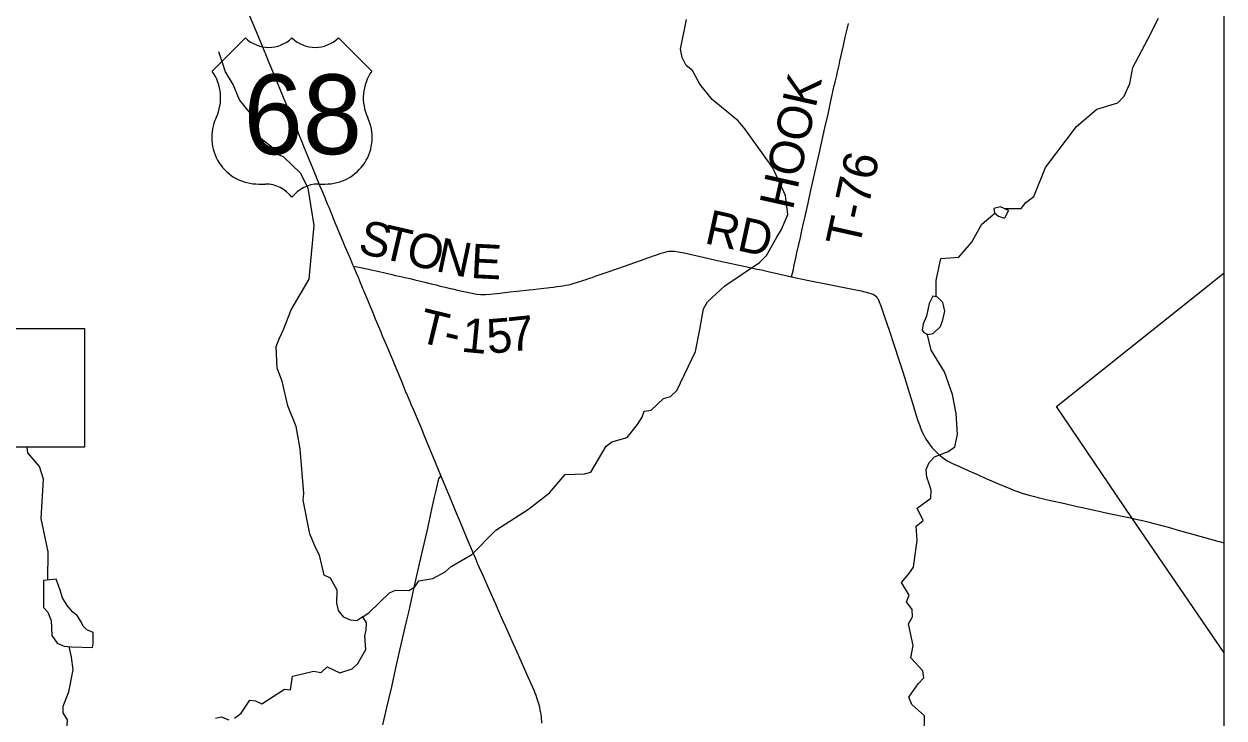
# Model space of a CAD drawing. Extents: x 0 to 34, y 0 to 22.
# Drawn here: x 14.353 to 16.337, y 19.117 to 20.264 of the extents above; entities that cross this region are included whole.
import ezdxf

# ---------------------------------------------------------------- set-up
doc = ezdxf.new("R2010")
doc.units = 0
for name, color, linetype in [('GM_X_Corporation', 7, 'Continuous'), ('GM_X_County_Road', 7, 'Continuous'), ('GM_X_Minor_Lake', 7, 'Continuous'), ('GM_X_Minor_River', 7, 'Continuous'), ('GM_X_Township_Road', 7, 'Continuous'), ('GM_X_Township_Road_Text', 7, 'Continuous'), ('GM_X_US_Location', 7, 'Continuous'), ('GM_X_US_Route', 7, 'Continuous'), ('GM_X_US_Shield', 7, 'Continuous'), ('SH_Text', 7, 'Continuous')]:
    doc.layers.add(name, color=color, linetype=linetype)

msp = doc.modelspace()

# ---------------------------------------------------------------- linework, layer by layer
at = {"layer": 'GM_X_Corporation'}
msp.add_lwpolyline([(16.3375, 14.3932), (16.3375, 21.1059), (9.5375, 21.1059), (9.5375, 15.0426), (9.5452, 15.0418), (9.7185, 15.0258), (10.2502, 14.9799), (10.3112, 14.9746), (10.787, 14.9212), (11.3129, 14.8754), (11.3292, 14.8742), (12.1361, 14.7923), (13.6754, 14.6095), (14.714, 14.5341), (15.778, 14.4476), (16.0263, 14.4243)], close=True, dxfattribs=at)
msp.add_lwpolyline([(16.3375, 19.0766), (16.3375, 19.2248), (16.1853, 19.4477), (16.0606, 19.6317), (16.3375, 19.8528), (16.3375, 21.1059)], dxfattribs=at)
at = {"layer": 'GM_X_County_Road'}
msp.add_lwpolyline([(14.9461, 19.1058), (14.9528, 19.1341), (14.9567, 19.1503), (14.9609, 19.1685), (14.9671, 19.197), (14.9734, 19.2242), (14.9832, 19.2672), (14.9859, 19.2787), (14.9891, 19.2918), (14.995, 19.3172), (14.9983, 19.3324), (15.0016, 19.3475), (15.007, 19.3718), (15.0151, 19.4069), (15.0193, 19.4257), (15.0221, 19.4384), (15.025, 19.4517), (15.028, 19.465), (15.0285, 19.4674), (15.0318, 19.482), (15.0338, 19.491), (15.0366, 19.5031), (15.0384, 19.5102), (15.0391, 19.5122), (15.0398, 19.5138), (15.0421, 19.5179)], dxfattribs=at)
at = {"layer": 'GM_X_Minor_Lake'}
for points in [[(15.9809, 19.9558), (15.9681, 19.9621), (15.957, 19.9593), (15.958, 19.952), (15.9644, 19.9466), (15.9742, 19.9434)], [(15.9809, 19.9558), (15.9742, 19.9434)], [(15.8567, 19.7525), (15.8686, 19.7641), (15.8726, 19.7754), (15.8759, 19.7894), (15.8727, 19.8039), (15.8638, 19.8128), (15.8558, 19.8144), (15.8499, 19.802), (15.8454, 19.7812), (15.8399, 19.7687)], [(15.8399, 19.7687), (15.8381, 19.7579), (15.8408, 19.7543), (15.8473, 19.7508), (15.8567, 19.7525)], [(14.4674, 19.2401), (14.4669, 19.2584), (14.4564, 19.2627), (14.4508, 19.2689), (14.4471, 19.2758), (14.4408, 19.2862), (14.4337, 19.292), (14.4244, 19.3031), (14.4163, 19.3158), (14.4127, 19.3284), (14.4058, 19.3464), (14.3848, 19.3441), (14.3848, 19.2993), (14.3923, 19.2919), (14.3978, 19.2782), (14.3989, 19.2531), (14.4078, 19.2404), (14.4191, 19.2356), (14.4312, 19.2347)], [(14.4312, 19.2347), (14.4663, 19.2332), (14.4674, 19.2401)]]:
    msp.add_lwpolyline(points, dxfattribs=at)
at = {"layer": 'GM_X_Minor_River'}
for points in [[(14.9131, 19.2841), (14.9239, 19.2912), (14.9571, 19.3236), (14.967, 19.328), (14.9894, 19.3276), (14.999, 19.3339), (15.006, 19.3437), (15.0292, 19.3478), (15.0495, 19.3585), (15.0592, 19.3674), (15.0933, 19.387), (15.1331, 19.4277), (15.1869, 19.4621), (15.2219, 19.4892), (15.2478, 19.5195), (15.2797, 19.5205), (15.29, 19.5234), (15.3155, 19.5666), (15.3251, 19.5733), (15.3503, 19.5808), (15.3677, 19.6022), (15.3751, 19.6142), (15.3783, 19.6244), (15.3901, 19.6257), (15.4106, 19.6451), (15.422, 19.6487), (15.4325, 19.6584), (15.4632, 19.7228), (15.4706, 19.7591), (15.4765, 19.7932), (15.4832, 19.8052), (15.5121, 19.8317), (15.5694, 19.8702), (15.5806, 19.8818), (15.5978, 19.9122), (15.6056, 19.9246), (15.6159, 19.9492), (15.6123, 19.9811), (15.5914, 20.0267), (15.545, 20.0912), (15.5342, 20.1043), (15.4908, 20.1396), (15.4704, 20.1647), (15.4586, 20.1873), (15.4481, 20.1958), (15.4411, 20.2092), (15.4387, 20.2229), (15.4486, 20.2718)], [(15.9738, 19.9593), (16.0018, 19.9592), (16.0096, 19.9694), (16.0227, 19.979), (16.0421, 20.0269), (16.0934, 20.0951), (16.1269, 20.1238), (16.162, 20.1338), (16.1724, 20.145), (16.1815, 20.1658), (16.1865, 20.1923), (16.2113, 20.2393), (16.2289, 20.2743)], [(14.701, 19.1165), (14.7118, 19.1251), (14.7262, 19.1461), (14.7357, 19.1455), (14.7459, 19.1404), (14.7835, 19.1645), (14.7937, 19.1635), (14.7971, 19.1863), (14.8109, 19.1894), (14.8318, 19.1944), (14.8443, 19.1923), (14.8544, 19.2016), (14.8751, 19.1914), (14.8953, 19.1979), (14.9049, 19.2068), (14.9179, 19.2301), (14.9164, 19.2522), (14.9184, 19.262), (14.919, 19.2742), (14.9131, 19.2841), (14.9035, 19.2778), (14.8925, 19.2784), (14.8816, 19.2835), (14.873, 19.2947), (14.8702, 19.3069), (14.8706, 19.3282), (14.8595, 19.3481), (14.849, 19.3528), (14.8416, 19.386), (14.8346, 19.3986), (14.8255, 19.4216), (14.8143, 19.4772), (14.8156, 19.4882), (14.8093, 19.562), (14.8027, 19.5989), (14.7892, 19.633), (14.78, 19.6741), (14.7717, 19.6955), (14.77, 19.7309), (14.7756, 19.7452), (14.7819, 19.7592), (14.7946, 19.7916), (14.8243, 19.8424), (14.8327, 19.9311), (14.8227, 19.9928), (14.8102, 20.018), (14.7822, 20.0447), (14.772, 20.0487), (14.7627, 20.061), (14.7399, 20.0785), (14.7346, 20.1052), (14.728, 20.1159), (14.7094, 20.139), (14.6988, 20.1646), (14.6859, 20.1854), (14.6751, 20.2186)], [(15.8612, 19.8133), (15.8612, 19.8405), (15.869, 19.8765), (15.8987, 19.879), (15.92, 19.9029), (15.9368, 19.9334), (15.9587, 19.9514)], [(15.8416, 19.0905), (15.8424, 19.1205), (15.8211, 19.1391), (15.816, 19.1513), (15.8316, 19.1734), (15.8412, 19.1835), (15.8395, 19.195), (15.8198, 19.2162), (15.8232, 19.2366), (15.8154, 19.2728), (15.8225, 19.2841), (15.8219, 19.2963), (15.8123, 19.309), (15.8166, 19.3199), (15.8041, 19.341), (15.8161, 19.3552), (15.8242, 19.3661), (15.8299, 19.4108), (15.8281, 19.434), (15.84, 19.4433), (15.8301, 19.464), (15.8528, 19.4803), (15.8534, 19.4936), (15.8501, 19.5039), (15.8458, 19.5153), (15.8448, 19.5275), (15.85, 19.5392), (15.8589, 19.5489), (15.8814, 19.5576), (15.8922, 19.5651), (15.8967, 19.5859), (15.8943, 19.6205), (15.8884, 19.6517), (15.8753, 19.6895), (15.8532, 19.7252), (15.8468, 19.7527)], [(14.3919, 19.3449), (14.3929, 19.3918), (14.3813, 19.4467), (14.3851, 19.5119), (14.3786, 19.5329), (14.3592, 19.5553), (14.3579, 19.5648)], [(14.4628, 19.0015), (14.4475, 19.0107), (14.4245, 19.0419), (14.4206, 19.0571), (14.4249, 19.1137), (14.4176, 19.1252), (14.4174, 19.1366), (14.4269, 19.1599), (14.434, 19.1963), (14.4313, 19.2176), (14.4274, 19.235)], [(14.6695, 19.1167), (14.679, 19.1188), (14.6915, 19.1136)]]:
    msp.add_lwpolyline(points, dxfattribs=at)
at = {"layer": 'GM_X_Township_Road'}
for points in [[(15.6224, 19.8463), (15.6252, 19.8586), (15.6262, 19.8635), (15.6287, 19.875), (15.6311, 19.8859), (15.6342, 19.8999), (15.6368, 19.9114), (15.6393, 19.9229), (15.642, 19.935), (15.6441, 19.9441), (15.6452, 19.949), (15.6497, 19.9682), (15.6544, 19.9895), (15.663, 20.0283), (15.6678, 20.0495), (15.6775, 20.0925), (15.6826, 20.1156), (15.6873, 20.1374), (15.6895, 20.1471), (15.6913, 20.155), (15.693, 20.1629), (15.6943, 20.1683), (15.6953, 20.1725), (15.6969, 20.1792), (15.6983, 20.1852), (15.7008, 20.1961), (15.7022, 20.2028), (15.7079, 20.2289), (15.7111, 20.2428), (15.7136, 20.2537), (15.7146, 20.258), (15.7163, 20.2652)], [(14.8976, 19.8642), (14.9072, 19.8621), (14.92, 19.8594), (14.94, 19.8549), (14.9493, 19.8527), (14.9611, 19.8502), (14.9673, 19.8488), (14.9732, 19.8475), (14.9833, 19.8451), (14.9936, 19.8428), (14.999, 19.8415), (15.0065, 19.8397), (15.0155, 19.8375), (15.0262, 19.8348), (15.0342, 19.8329), (15.0396, 19.8315), (15.0517, 19.8286), (15.0583, 19.8271), (15.0613, 19.8264), (15.0722, 19.8239), (15.0831, 19.8214), (15.0909, 19.8197), (15.0938, 19.8191), (15.0985, 19.8183), (15.1021, 19.8178), (15.1085, 19.8173), (15.1123, 19.8172), (15.1159, 19.8173), (15.1239, 19.8177), (15.1344, 19.8188), (15.1399, 19.8195), (15.1442, 19.82), (15.1565, 19.8213), (15.1677, 19.8225), (15.1883, 19.8248), (15.1949, 19.8256), (15.2034, 19.8266), (15.2127, 19.8276), (15.2182, 19.8281), (15.2225, 19.8286), (15.2287, 19.8294), (15.2339, 19.8301), (15.2403, 19.8309), (15.2441, 19.8316), (15.2488, 19.8323), (15.2534, 19.8332), (15.2576, 19.8343), (15.2643, 19.8362), (15.2667, 19.837), (15.2697, 19.8379), (15.2724, 19.8387), (15.2754, 19.8397), (15.2789, 19.8409), (15.2828, 19.8422), (15.2879, 19.8439), (15.2922, 19.8454), (15.2977, 19.8473), (15.314, 19.8529), (15.3367, 19.8608), (15.3725, 19.8733), (15.383, 19.877), (15.3986, 19.8826), (15.4067, 19.8854), (15.4133, 19.8874), (15.4167, 19.8882), (15.4193, 19.8886), (15.4247, 19.8889), (15.4286, 19.8887), (15.4345, 19.8879), (15.4381, 19.8872), (15.4444, 19.8859), (15.4709, 19.8799), (15.5019, 19.8728), (15.5202, 19.8689), (15.5512, 19.8623), (15.5627, 19.8598), (15.5724, 19.8578), (15.5858, 19.8548), (15.5936, 19.853), (15.6224, 19.8463)], [(15.6224, 19.8463), (15.6483, 19.8411), (15.6872, 19.833), (15.7201, 19.8264), (15.7372, 19.823), (15.7497, 19.82), (15.7536, 19.8188), (15.7566, 19.8178), (15.759, 19.8165), (15.761, 19.815), (15.7621, 19.8139), (15.7635, 19.8124), (15.7648, 19.8105), (15.7661, 19.8081), (15.7674, 19.8051), (15.77, 19.7986), (15.7766, 19.7785), (15.7835, 19.7579), (15.7919, 19.7326), (15.8009, 19.7056), (15.8057, 19.691), (15.8118, 19.6716), (15.8164, 19.6568), (15.8202, 19.6445), (15.8308, 19.6101), (15.8348, 19.599)], [(15.8348, 19.599), (15.8352, 19.5979), (15.839, 19.5883), (15.8409, 19.5843), (15.8439, 19.5789), (15.8485, 19.5717), (15.8545, 19.564), (15.8602, 19.558), (15.8656, 19.5526), (15.8715, 19.5479), (15.8797, 19.5423), (15.8884, 19.5376), (15.8999, 19.5325), (15.9156, 19.5256)], [(15.9156, 19.5256), (15.9258, 19.5212), (15.9405, 19.5146), (15.962, 19.5054), (15.9833, 19.4965), (15.9908, 19.4933), (15.996, 19.4913), (16.0003, 19.4897), (16.0055, 19.488), (16.0152, 19.4851), (16.0242, 19.4829), (16.032, 19.481), (16.0368, 19.4799), (16.0434, 19.4783), (16.0483, 19.4772), (16.0743, 19.4713), (16.0949, 19.4667), (16.1058, 19.4644), (16.1179, 19.4617), (16.1313, 19.4588), (16.1398, 19.4569), (16.1531, 19.454), (16.1719, 19.4499), (16.1855, 19.4471)], [(16.1855, 19.4471), (16.1889, 19.4464), (16.2028, 19.4433), (16.2094, 19.4417), (16.2473, 19.4316), (16.258, 19.4286), (16.3273, 19.4091), (16.3375, 19.4063)]]:
    msp.add_lwpolyline(points, dxfattribs=at)
at = {"layer": 'GM_X_US_Route'}
msp.add_lwpolyline([(15.209, 19.1081), (15.2084, 19.1187), (15.208, 19.1222), (15.2076, 19.1254), (15.2067, 19.1302), (15.2057, 19.1346), (15.2043, 19.1404), (15.2023, 19.147), (15.1997, 19.1542), (15.1982, 19.1581), (15.197, 19.161), (15.1943, 19.1672), (15.1915, 19.1735), (15.1846, 19.1892), (15.1749, 19.2109), (15.1683, 19.2257), (15.1625, 19.2388), (15.1542, 19.2575), (15.1519, 19.2625), (15.1496, 19.2676), (15.1453, 19.2772), (15.137, 19.2959), (15.1329, 19.305), (15.1226, 19.3283), (15.1166, 19.3419), (15.1114, 19.3538), (15.1063, 19.3652), (15.1036, 19.3714), (15.0999, 19.3799), (15.0977, 19.3851), (15.0945, 19.3925), (15.0858, 19.4131), (15.0746, 19.44), (15.0664, 19.4595), (15.0568, 19.4827), (15.0434, 19.5149), (15.0421, 19.5179), (15.0293, 19.5487), (15.017, 19.5789), (15.0094, 19.5972), (15.0034, 19.6115), (14.9967, 19.6269), (14.9932, 19.6355), (14.992, 19.6384), (14.9869, 19.6504), (14.984, 19.6573), (14.9774, 19.6733), (14.9699, 19.6917), (14.9655, 19.702), (14.9626, 19.7089), (14.9587, 19.718), (14.9548, 19.7271), (14.951, 19.7363), (14.9459, 19.7483), (14.9433, 19.7546), (14.9378, 19.7677), (14.9342, 19.7763), (14.9295, 19.7878), (14.9247, 19.7993), (14.9212, 19.8079), (14.9181, 19.8153), (14.9148, 19.8233), (14.9092, 19.8365), (14.9058, 19.8451), (14.9025, 19.8525), (14.8976, 19.8642), (14.8967, 19.8662), (14.8931, 19.8748), (14.8869, 19.8897), (14.8841, 19.8959), (14.8808, 19.904), (14.8649, 19.9424), (14.863, 19.947), (14.8573, 19.9608), (14.8549, 19.9665), (14.8502, 19.978), (14.8459, 19.9883), (14.8428, 19.9958), (14.8315, 20.0233), (14.8223, 20.0458), (14.8168, 20.0589), (14.8126, 20.0693), (14.8072, 20.0825), (14.8054, 20.0871), (14.8033, 20.0923), (14.795, 20.1124), (14.7892, 20.1258), (14.7848, 20.1364), (14.7822, 20.1427), (14.7782, 20.1525), (14.771, 20.1697), (14.7679, 20.1771), (14.7643, 20.1857), (14.7598, 20.1966), (14.7567, 20.204), (14.7525, 20.2143), (14.7512, 20.2178), (14.7401, 20.2448), (14.7225, 20.2866)], dxfattribs=at)
at = {"layer": 'GM_X_US_Shield'}
for p, q in [((14.719, 20.2415), (14.6641, 20.1866)), ((14.9278, 20.1866), (14.8728, 20.2415)), ((14.741, 19.9998), (14.752, 19.9998)), ((14.8399, 19.9998), (14.8509, 19.9998))]:
    msp.add_line(p, q, dxfattribs=at)
for centre, radius, start, end in [((14.7575, 20.2807), 0.0549, 225.573, 314.427), ((14.8344, 20.2807), 0.0549, 225.573, 314.427), ((14.6011, 20.1425), 0.0769, 334.5471, 35.0009), ((14.9908, 20.1425), 0.0769, 144.9991, 205.4529), ((14.7401, 20.0767), 0.0769, 154.8319, 270.6383), ((14.8517, 20.0767), 0.0769, 269.3617, 25.1681), ((14.752, 19.9449), 0.0549, 36.8699, 90), ((14.8399, 19.9449), 0.0549, 90, 143.1301)]:
    msp.add_arc(centre, radius, start, end, dxfattribs=at)
at = {"layer": 'SH_Text'}
msp.add_lwpolyline([(13.1377, 19.7608), (14.4527, 19.7608), (14.4527, 19.5648), (13.1377, 19.5648)], close=True, dxfattribs=at)

# ---------------------------------------------------------------- texts
at = {"layer": 'GM_X_Township_Road_Text'}
for s, height, rotation, p in [('HOOK', 0.05682, 77.3933, (15.6241, 19.9553)), ('T-76', 0.05682, 77.3962, (15.7339, 19.8926)), ('RD', 0.05682, 347.6323, (15.4765, 19.9023)), ('S', 0.0568, 346.8223, (14.9034, 19.8864)), ('T', 0.0568, 346.8213, (14.9407, 19.8777)), ('O', 0.0568, 346.8262, (14.9821, 19.868)), ('N', 0.0568, 347.9743, (15.032, 19.8563)), ('E', 0.0568, 357.0864, (15.0907, 19.8446)), ('T', 0.0568, 346.3099, (15.0018, 19.7396)), ('1', 0.0568, 354.5126, (15.0746, 19.7228)), ('5', 0.0568, 4.5371, (15.1202, 19.7193)), ('7', 0.0568, 6.1146, (15.1568, 19.7223)), ('-', 0.0568, 346.7717, (15.0436, 19.7295))]:
    msp.add_text(s, height=height, rotation=rotation, dxfattribs=at).set_placement(p)
at = {"layer": 'GM_X_US_Location'}
for s in ['0', '/']:
    msp.add_text(s, height=0.000189, dxfattribs=at).set_placement((14.7959, 20.1141))
msp.add_text('68', height=0.000189, rotation=0, dxfattribs=at).set_placement((14.7568, 20.0749))
at = {"layer": 'GM_X_US_Shield'}
msp.add_text('68', height=0.13184, dxfattribs=at).set_placement((14.7157, 20.0492))

doc.saveas('drawing.dxf')
